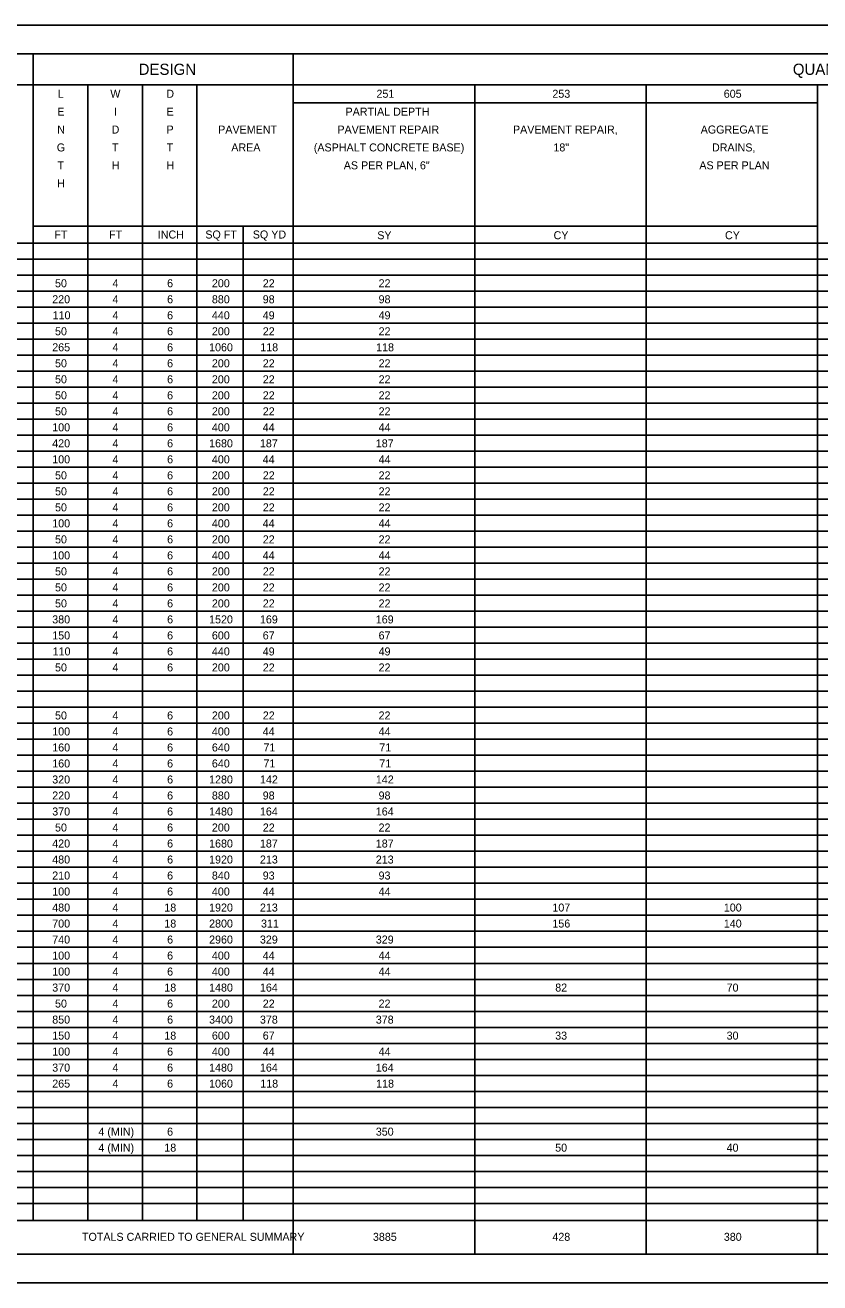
# Model space of a CAD drawing. Extents: x 0 to 34, y 0 to 22.
# Drawn here: x 8.44 to 22.34, y 0 to 22 of the extents above; entities that cross this region are included whole.
import ezdxf

# ---------------------------------------------------------------- set-up
doc = ezdxf.new("R2010")
doc.units = 0
for name, color, linetype in [('SH_Border', 7, 'Continuous'), ('SH_Cut_Line', 7, 'Continuous'), ('SH_Data', 7, 'Continuous')]:
    doc.layers.add(name, color=color, linetype=linetype)

msp = doc.modelspace()

# ---------------------------------------------------------------- linework, layer by layer
at = {"layer": 'SH_Border'}
msp.add_lwpolyline([(1.5, 21.5), (33.5, 21.5), (33.5, 0.5), (1.5, 0.5)], close=True, dxfattribs=at)
at = {"layer": 'SH_Cut_Line'}
msp.add_lwpolyline([(0, 0), (34, 0), (34, 22), (0, 22)], close=True, dxfattribs=at)
at = {"layer": 'SH_Data'}
for p, q in [((8.582, 21.5), (8.582, 1.093)), ((13.128, 21.5), (13.128, 0.516)), ((1.5, 20.956), (32.004, 20.956)), ((9.538, 20.956), (9.538, 1.093)), ((10.493, 20.956), (10.493, 1.093)), ((11.448, 20.956), (11.448, 1.093)), ((16.307, 20.956), (16.307, 0.516)), ((19.305, 20.956), (19.305, 0.516)), ((22.302, 20.956), (22.302, 0.516)), ((13.128, 20.644), (22.302, 20.644)), ((8.582, 18.486), (22.302, 18.486)), ((12.255, 18.486), (12.255, 1.093)), ((1.5, 18.189), (32.004, 18.189)), ((1.5, 17.909), (32.004, 17.909)), ((1.5, 17.629), (32.004, 17.629)), ((1.5, 17.349), (32.004, 17.349)), ((1.5, 17.069), (32.004, 17.069)), ((1.5, 16.789), (32.004, 16.789)), ((1.5, 16.509), (32.004, 16.509)), ((1.5, 16.229), (32.004, 16.229)), ((1.5, 15.949), (32.004, 15.949)), ((1.5, 15.669), (32.004, 15.669)), ((1.5, 15.389), (32.004, 15.389)), ((1.5, 15.109), (32.004, 15.109)), ((1.5, 14.829), (32.004, 14.829)), ((1.5, 14.549), (32.004, 14.549)), ((1.5, 14.269), (32.004, 14.269)), ((1.5, 13.989), (32.004, 13.989)), ((1.5, 13.709), (32.004, 13.709)), ((1.5, 13.429), (32.004, 13.429)), ((1.5, 13.149), (32.004, 13.149)), ((1.5, 12.869), (32.004, 12.869)), ((1.5, 12.589), (32.004, 12.589)), ((1.5, 12.309), (32.004, 12.309)), ((1.5, 12.029), (32.004, 12.029)), ((1.5, 11.749), (32.004, 11.749)), ((1.5, 11.469), (32.004, 11.469)), ((1.5, 11.189), (32.004, 11.189)), ((1.5, 10.909), (32.004, 10.909)), ((1.5, 10.629), (32.004, 10.629)), ((1.5, 10.349), (32.004, 10.349)), ((1.5, 10.069), (32.004, 10.069)), ((1.5, 9.789), (32.004, 9.789)), ((1.5, 9.509), (32.004, 9.509)), ((1.5, 9.229), (32.004, 9.229)), ((1.5, 8.949), (32.004, 8.949)), ((1.5, 8.669), (32.004, 8.669)), ((1.5, 8.389), (32.004, 8.389)), ((1.5, 8.109), (32.004, 8.109)), ((1.5, 7.829), (32.004, 7.829)), ((1.5, 7.549), (32.004, 7.549)), ((1.5, 7.269), (32.004, 7.269)), ((1.5, 6.989), (32.004, 6.989)), ((1.5, 6.709), (32.004, 6.709)), ((1.5, 6.429), (32.004, 6.429)), ((1.5, 6.149), (32.004, 6.149)), ((1.5, 5.869), (32.004, 5.869)), ((1.5, 5.589), (32.004, 5.589)), ((1.5, 5.309), (32.004, 5.309)), ((1.5, 5.029), (32.004, 5.029)), ((1.5, 4.749), (32.004, 4.749)), ((1.5, 4.469), (32.004, 4.469)), ((1.5, 4.189), (32.004, 4.189)), ((1.5, 3.909), (32.004, 3.909)), ((1.5, 3.629), (32.004, 3.629)), ((1.5, 3.349), (32.004, 3.349)), ((1.5, 3.069), (32.004, 3.069)), ((1.5, 2.789), (32.004, 2.789)), ((1.5, 2.509), (32.004, 2.509)), ((1.5, 2.229), (32.004, 2.229)), ((1.5, 1.949), (32.004, 1.949)), ((1.5, 1.669), (32.004, 1.669)), ((1.5, 1.389), (32.004, 1.389)), ((1.5, 1.093), (32.004, 1.093))]:
    msp.add_line(p, q, dxfattribs=at)

# ---------------------------------------------------------------- texts
for s, height, p in [('DESIGN', 0.196, (10.428, 21.13)), ('QUANTITIES', 0.196, (21.868, 21.13)), ('L', 0.14, (9.014, 20.73)), ('W', 0.14, (9.933, 20.73)), ('D', 0.14, (10.912, 20.73)), ('251', 0.14, (14.587, 20.73)), ('253', 0.14, (17.663, 20.73)), ('605', 0.14, (20.66, 20.73)), ('E', 0.14, (9.006, 20.417)), ('I', 0.14, (9.999, 20.417)), ('E', 0.14, (10.917, 20.417)), ('PARTIAL DEPTH', 0.14, (14.046, 20.417)), ('N', 0.14, (9.004, 20.104)), ('D', 0.14, (9.956, 20.104)), ('P', 0.14, (10.916, 20.104)), ('PAVEMENT', 0.14, (11.819, 20.104)), ('PAVEMENT REPAIR', 0.14, (13.904, 20.104)), ('PAVEMENT REPAIR,', 0.14, (16.974, 20.104)), ('AGGREGATE', 0.14, (20.257, 20.104)), ('G', 0.14, (8.997, 19.791)), ('T', 0.14, (9.963, 19.791)), ('T', 0.14, (10.919, 19.791)), ('AREA', 0.14, (12.048, 19.791)), ('(ASPHALT CONCRETE BASE)', 0.14, (13.491, 19.791)), ('18"', 0.14, (17.681, 19.791)), ('DRAINS,', 0.14, (20.454, 19.791)), ('T', 0.14, (9.008, 19.478)), ('H', 0.14, (9.959, 19.478)), ('H', 0.14, (10.914, 19.478)), ('AS PER PLAN, 6"', 0.14, (14.015, 19.478)), ('AS PER PLAN', 0.14, (20.233, 19.478)), ('H', 0.14, (9.004, 19.165)), ('FT', 0.14, (8.954, 18.268)), ('FT', 0.14, (9.91, 18.268)), ('INCH', 0.14, (10.763, 18.268)), ('SQ FT', 0.14, (11.594, 18.268)), ('SQ YD', 0.14, (12.424, 18.268)), ('SY', 0.14, (14.601, 18.255)), ('CY', 0.14, (17.684, 18.255)), ('CY', 0.14, (20.682, 18.255)), ('50', 0.14, (8.966, 17.415)), ('4', 0.14, (9.971, 17.415)), ('6', 0.14, (10.926, 17.415)), ('200', 0.14, (11.709, 17.415)), ('22', 0.14, (12.599, 17.415)), ('22', 0.14, (14.624, 17.415)), ('220', 0.14, (8.917, 17.135)), ('4', 0.14, (9.971, 17.135)), ('6', 0.14, (10.926, 17.135)), ('880', 0.14, (11.709, 17.135)), ('98', 0.14, (12.598, 17.135)), ('98', 0.14, (14.624, 17.135)), ('110', 0.14, (8.924, 16.855)), ('4', 0.14, (9.971, 16.855)), ('6', 0.14, (10.926, 16.855)), ('440', 0.14, (11.709, 16.855)), ('49', 0.14, (12.598, 16.855)), ('49', 0.14, (14.624, 16.855)), ('50', 0.14, (8.966, 16.575)), ('4', 0.14, (9.971, 16.575)), ('6', 0.14, (10.926, 16.575)), ('200', 0.14, (11.709, 16.575)), ('22', 0.14, (12.599, 16.575)), ('22', 0.14, (14.624, 16.575)), ('265', 0.14, (8.917, 16.295)), ('4', 0.14, (9.971, 16.295)), ('6', 0.14, (10.926, 16.295)), ('1060', 0.14, (11.66, 16.295)), ('118', 0.14, (12.555, 16.295)), ('118', 0.14, (14.581, 16.295)), ('50', 0.14, (8.966, 16.015)), ('4', 0.14, (9.971, 16.015)), ('6', 0.14, (10.926, 16.015)), ('200', 0.14, (11.709, 16.015)), ('22', 0.14, (12.599, 16.015)), ('22', 0.14, (14.624, 16.015)), ('50', 0.14, (8.966, 15.735)), ('4', 0.14, (9.971, 15.735)), ('6', 0.14, (10.926, 15.735)), ('200', 0.14, (11.709, 15.735)), ('22', 0.14, (12.599, 15.735)), ('22', 0.14, (14.624, 15.735)), ('50', 0.14, (8.966, 15.455)), ('4', 0.14, (9.971, 15.455)), ('6', 0.14, (10.926, 15.455)), ('200', 0.14, (11.709, 15.455)), ('22', 0.14, (12.599, 15.455)), ('22', 0.14, (14.624, 15.455)), ('50', 0.14, (8.966, 15.175)), ('4', 0.14, (9.971, 15.175)), ('6', 0.14, (10.926, 15.175)), ('200', 0.14, (11.709, 15.175)), ('22', 0.14, (12.599, 15.175)), ('22', 0.14, (14.624, 15.175)), ('100', 0.14, (8.917, 14.895)), ('4', 0.14, (9.971, 14.895)), ('6', 0.14, (10.926, 14.895)), ('400', 0.14, (11.709, 14.895)), ('44', 0.14, (12.598, 14.895)), ('44', 0.14, (14.624, 14.895)), ('420', 0.14, (8.917, 14.615)), ('4', 0.14, (9.971, 14.615)), ('6', 0.14, (10.926, 14.615)), ('1680', 0.14, (11.66, 14.615)), ('187', 0.14, (12.549, 14.615)), ('187', 0.14, (14.575, 14.615)), ('100', 0.14, (8.917, 14.335)), ('4', 0.14, (9.971, 14.335)), ('6', 0.14, (10.926, 14.335)), ('400', 0.14, (11.709, 14.335)), ('44', 0.14, (12.598, 14.335)), ('44', 0.14, (14.624, 14.335)), ('50', 0.14, (8.966, 14.055)), ('4', 0.14, (9.971, 14.055)), ('6', 0.14, (10.926, 14.055)), ('200', 0.14, (11.709, 14.055)), ('22', 0.14, (12.599, 14.055)), ('22', 0.14, (14.624, 14.055)), ('50', 0.14, (8.966, 13.775)), ('4', 0.14, (9.971, 13.775)), ('6', 0.14, (10.926, 13.775)), ('200', 0.14, (11.709, 13.775)), ('22', 0.14, (12.599, 13.775)), ('22', 0.14, (14.624, 13.775)), ('50', 0.14, (8.966, 13.495)), ('4', 0.14, (9.971, 13.495)), ('6', 0.14, (10.926, 13.495)), ('200', 0.14, (11.709, 13.495)), ('22', 0.14, (12.599, 13.495)), ('22', 0.14, (14.624, 13.495)), ('100', 0.14, (8.917, 13.215)), ('4', 0.14, (9.971, 13.215)), ('6', 0.14, (10.926, 13.215)), ('400', 0.14, (11.709, 13.215)), ('44', 0.14, (12.598, 13.215)), ('44', 0.14, (14.624, 13.215)), ('50', 0.14, (8.966, 12.935)), ('4', 0.14, (9.971, 12.935)), ('6', 0.14, (10.926, 12.935)), ('200', 0.14, (11.709, 12.935)), ('22', 0.14, (12.599, 12.935)), ('22', 0.14, (14.624, 12.935)), ('100', 0.14, (8.917, 12.655)), ('4', 0.14, (9.971, 12.655)), ('6', 0.14, (10.926, 12.655)), ('400', 0.14, (11.709, 12.655)), ('44', 0.14, (12.598, 12.655)), ('44', 0.14, (14.624, 12.655)), ('50', 0.14, (8.966, 12.375)), ('4', 0.14, (9.971, 12.375)), ('6', 0.14, (10.926, 12.375)), ('200', 0.14, (11.709, 12.375)), ('22', 0.14, (12.599, 12.375)), ('22', 0.14, (14.624, 12.375)), ('50', 0.14, (8.966, 12.095)), ('4', 0.14, (9.971, 12.095)), ('6', 0.14, (10.926, 12.095)), ('200', 0.14, (11.709, 12.095)), ('22', 0.14, (12.599, 12.095)), ('22', 0.14, (14.624, 12.095)), ('50', 0.14, (8.966, 11.815)), ('4', 0.14, (9.971, 11.815)), ('6', 0.14, (10.926, 11.815)), ('200', 0.14, (11.709, 11.815)), ('22', 0.14, (12.599, 11.815)), ('22', 0.14, (14.624, 11.815)), ('380', 0.14, (8.917, 11.535)), ('4', 0.14, (9.971, 11.535)), ('6', 0.14, (10.926, 11.535)), ('1520', 0.14, (11.66, 11.535)), ('169', 0.14, (12.549, 11.535)), ('169', 0.14, (14.575, 11.535)), ('150', 0.14, (8.917, 11.255)), ('4', 0.14, (9.971, 11.255)), ('6', 0.14, (10.926, 11.255)), ('600', 0.14, (11.709, 11.255)), ('67', 0.14, (12.598, 11.255)), ('67', 0.14, (14.624, 11.255)), ('110', 0.14, (8.924, 10.975)), ('4', 0.14, (9.971, 10.975)), ('6', 0.14, (10.926, 10.975)), ('440', 0.14, (11.709, 10.975)), ('49', 0.14, (12.598, 10.975)), ('49', 0.14, (14.624, 10.975)), ('50', 0.14, (8.966, 10.695)), ('4', 0.14, (9.971, 10.695)), ('6', 0.14, (10.926, 10.695)), ('200', 0.14, (11.709, 10.695)), ('22', 0.14, (12.599, 10.695)), ('22', 0.14, (14.624, 10.695)), ('50', 0.14, (8.966, 9.855)), ('4', 0.14, (9.971, 9.855)), ('6', 0.14, (10.926, 9.855)), ('200', 0.14, (11.709, 9.855)), ('22', 0.14, (12.599, 9.855)), ('22', 0.14, (14.624, 9.855)), ('100', 0.14, (8.917, 9.575)), ('4', 0.14, (9.971, 9.575)), ('6', 0.14, (10.926, 9.575)), ('400', 0.14, (11.709, 9.575)), ('44', 0.14, (12.598, 9.575)), ('44', 0.14, (14.624, 9.575)), ('160', 0.14, (8.917, 9.295)), ('4', 0.14, (9.971, 9.295)), ('6', 0.14, (10.926, 9.295)), ('640', 0.14, (11.709, 9.295)), ('71', 0.14, (12.61, 9.295)), ('71', 0.14, (14.636, 9.295)), ('160', 0.14, (8.917, 9.015)), ('4', 0.14, (9.971, 9.015)), ('6', 0.14, (10.926, 9.015)), ('640', 0.14, (11.709, 9.015)), ('71', 0.14, (12.61, 9.015)), ('71', 0.14, (14.636, 9.015)), ('320', 0.14, (8.917, 8.735)), ('4', 0.14, (9.971, 8.735)), ('6', 0.14, (10.926, 8.735)), ('1280', 0.14, (11.66, 8.735)), ('142', 0.14, (12.55, 8.735)), ('142', 0.14, (14.576, 8.735)), ('220', 0.14, (8.917, 8.455)), ('4', 0.14, (9.971, 8.455)), ('6', 0.14, (10.926, 8.455)), ('880', 0.14, (11.709, 8.455)), ('98', 0.14, (12.598, 8.455)), ('98', 0.14, (14.624, 8.455)), ('370', 0.14, (8.917, 8.175)), ('4', 0.14, (9.971, 8.175)), ('6', 0.14, (10.926, 8.175)), ('1480', 0.14, (11.66, 8.175)), ('164', 0.14, (12.549, 8.175)), ('164', 0.14, (14.575, 8.175)), ('50', 0.14, (8.966, 7.895)), ('4', 0.14, (9.971, 7.895)), ('6', 0.14, (10.926, 7.895)), ('200', 0.14, (11.709, 7.895)), ('22', 0.14, (12.599, 7.895)), ('22', 0.14, (14.624, 7.895)), ('420', 0.14, (8.917, 7.615)), ('4', 0.14, (9.971, 7.615)), ('6', 0.14, (10.926, 7.615)), ('1680', 0.14, (11.66, 7.615)), ('187', 0.14, (12.549, 7.615)), ('187', 0.14, (14.575, 7.615)), ('480', 0.14, (8.917, 7.335)), ('4', 0.14, (9.971, 7.335)), ('6', 0.14, (10.926, 7.335)), ('1920', 0.14, (11.66, 7.335)), ('213', 0.14, (12.549, 7.335)), ('213', 0.14, (14.575, 7.335)), ('210', 0.14, (8.917, 7.055)), ('4', 0.14, (9.971, 7.055)), ('6', 0.14, (10.926, 7.055)), ('840', 0.14, (11.709, 7.055)), ('93', 0.14, (12.598, 7.055)), ('93', 0.14, (14.624, 7.055)), ('100', 0.14, (8.917, 6.775)), ('4', 0.14, (9.971, 6.775)), ('6', 0.14, (10.926, 6.775)), ('400', 0.14, (11.709, 6.775)), ('44', 0.14, (12.598, 6.775)), ('44', 0.14, (14.624, 6.775)), ('480', 0.14, (8.917, 6.495)), ('4', 0.14, (9.971, 6.495)), ('18', 0.14, (10.877, 6.495)), ('1920', 0.14, (11.66, 6.495)), ('213', 0.14, (12.549, 6.495)), ('107', 0.14, (17.663, 6.495)), ('100', 0.14, (20.661, 6.495)), ('700', 0.14, (8.917, 6.215)), ('4', 0.14, (9.971, 6.215)), ('18', 0.14, (10.877, 6.215)), ('2800', 0.14, (11.66, 6.215)), ('311', 0.14, (12.568, 6.215)), ('156', 0.14, (17.663, 6.215)), ('140', 0.14, (20.661, 6.215)), ('740', 0.14, (8.917, 5.935)), ('4', 0.14, (9.971, 5.935)), ('6', 0.14, (10.926, 5.935)), ('2960', 0.14, (11.66, 5.935)), ('329', 0.14, (12.549, 5.935)), ('329', 0.14, (14.575, 5.935)), ('100', 0.14, (8.917, 5.655)), ('4', 0.14, (9.971, 5.655)), ('6', 0.14, (10.926, 5.655)), ('400', 0.14, (11.709, 5.655)), ('44', 0.14, (12.598, 5.655)), ('44', 0.14, (14.624, 5.655)), ('100', 0.14, (8.917, 5.375)), ('4', 0.14, (9.971, 5.375)), ('6', 0.14, (10.926, 5.375)), ('400', 0.14, (11.709, 5.375)), ('44', 0.14, (12.598, 5.375)), ('44', 0.14, (14.624, 5.375)), ('370', 0.14, (8.917, 5.095)), ('4', 0.14, (9.971, 5.095)), ('18', 0.14, (10.877, 5.095)), ('1480', 0.14, (11.66, 5.095)), ('164', 0.14, (12.549, 5.095)), ('82', 0.14, (17.713, 5.095)), ('70', 0.14, (20.71, 5.095)), ('50', 0.14, (8.966, 4.815)), ('4', 0.14, (9.971, 4.815)), ('6', 0.14, (10.926, 4.815)), ('200', 0.14, (11.709, 4.815)), ('22', 0.14, (12.599, 4.815)), ('22', 0.14, (14.624, 4.815)), ('850', 0.14, (8.917, 4.535)), ('4', 0.14, (9.971, 4.535)), ('6', 0.14, (10.926, 4.535)), ('3400', 0.14, (11.66, 4.535)), ('378', 0.14, (12.549, 4.535)), ('378', 0.14, (14.575, 4.535)), ('150', 0.14, (8.917, 4.255)), ('4', 0.14, (9.971, 4.255)), ('18', 0.14, (10.877, 4.255)), ('600', 0.14, (11.709, 4.255)), ('67', 0.14, (12.598, 4.255)), ('33', 0.14, (17.712, 4.255)), ('30', 0.14, (20.71, 4.255)), ('100', 0.14, (8.917, 3.975)), ('4', 0.14, (9.971, 3.975)), ('6', 0.14, (10.926, 3.975)), ('400', 0.14, (11.709, 3.975)), ('44', 0.14, (12.598, 3.975)), ('44', 0.14, (14.624, 3.975)), ('370', 0.14, (8.917, 3.695)), ('4', 0.14, (9.971, 3.695)), ('6', 0.14, (10.926, 3.695)), ('1480', 0.14, (11.66, 3.695)), ('164', 0.14, (12.549, 3.695)), ('164', 0.14, (14.575, 3.695)), ('265', 0.14, (8.917, 3.415)), ('4', 0.14, (9.971, 3.415)), ('6', 0.14, (10.926, 3.415)), ('1060', 0.14, (11.66, 3.415)), ('118', 0.14, (12.555, 3.415)), ('118', 0.14, (14.581, 3.415)), ('4 (MIN)', 0.14, (9.725, 2.575)), ('6', 0.14, (10.926, 2.575)), ('350', 0.14, (14.575, 2.575)), ('4 (MIN)', 0.14, (9.725, 2.295)), ('18', 0.14, (10.877, 2.295)), ('50', 0.14, (17.712, 2.295)), ('40', 0.14, (20.71, 2.295)), ('TOTALS CARRIED TO GENERAL SUMMARY', 0.14, (9.437, 0.735)), ('3885', 0.14, (14.525, 0.735)), ('428', 0.14, (17.663, 0.735)), ('380', 0.14, (20.661, 0.735))]:
    msp.add_text(s, height=height, dxfattribs=at).set_placement(p)

doc.saveas('drawing.dxf')
